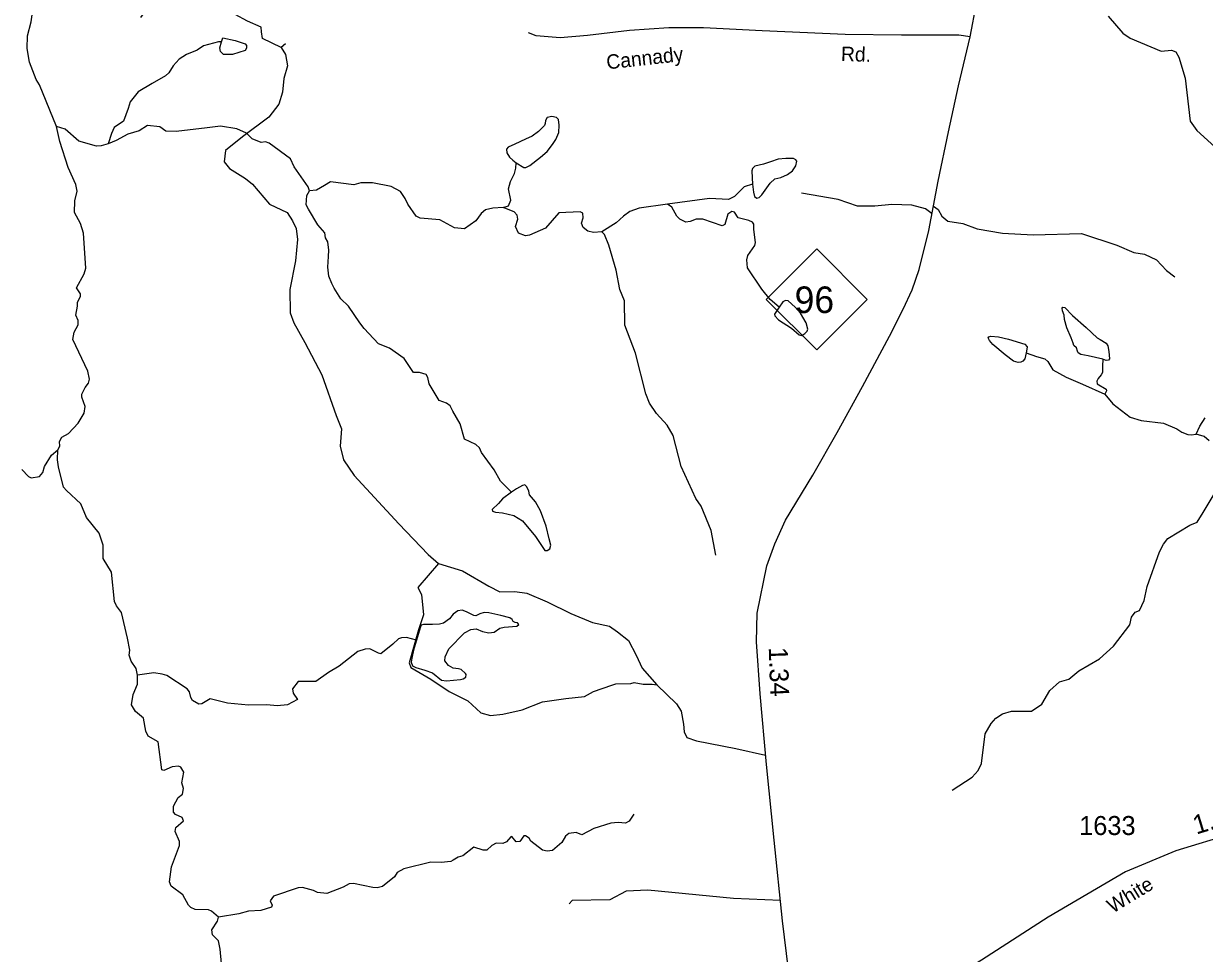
# Model space of a CAD drawing. Extents: x 2056842 to 2160602, y 826753 to 1016856.
# Drawn here: x 2118145 to 2125925, y 874725 to 880850 of the extents above; entities that cross this region are included whole.
import ezdxf

# ---------------------------------------------------------------- set-up
doc = ezdxf.new("R2010")
doc.units = 0
for name, color, linetype in [('Exist Hydrographic Creek Single Shore', 7, 'Continuous'), ('Exist Hydrographic Misc Water Feature', 7, 'Continuous'), ('Exist Road Non-System Type 51', 7, 'Continuous'), ('Exist Road Primary NC Attributed', 7, 'Continuous'), ('Exist Road Primary NC Service Mileage Hundredths English Label', 7, 'Continuous'), ('Exist Road Primary NC Shield CELL', 7, 'Continuous'), ('Exist Road Primary NC Shield Number Label', 7, 'Continuous'), ('Exist Road Secondary Mileage Hundredths English Label', 7, 'Continuous'), ('Exist Road Secondary Type 41 Attributed', 7, 'Continuous'), ('Exist Road Secondary Type 51 Attributed', 7, 'Continuous'), ('Exist Road Secondary Type 51 Label', 7, 'Continuous'), ('Exist Road Secondary Type 51 Number Label', 7, 'Continuous')]:
    doc.layers.add(name, color=color, linetype=linetype)

msp = doc.modelspace()

# ---------------------------------------------------------------- linework, layer by layer
at = {"layer": 'Exist Hydrographic Creek Single Shore'}
for points in [[(2118362.2, 880170.9), (2118249.1, 880446.6), (2118226.8, 880480.5), (2118184.3, 880596.2), (2118168.1, 880686.1), (2118171.8, 880770), (2118195.4, 880862.1), (2118245.6, 881212.4), (2118249.5, 881260.2), (2118281.3, 881336.4), (2118292.9, 881406.7), (2118336.4, 881494.7), (2118378, 881554.8), (2118441.9, 881629), (2118489.4, 881705.4), (2118644.8, 881889.9), (2118769.8, 882062.5), (2118845.2, 882200.7), (2118936.8, 882299.2), (2119076.3, 882413.8)], [(2120028, 879748.6), (2120020, 879774.5), (2119927.3, 879906.1), (2119903.1, 879958), (2119762.8, 880063.3), (2119738.8, 880071.2), (2119710.7, 880067.1), (2119650.5, 880090.8), (2119614.6, 880128.7), (2119550.2, 880156.3), (2119442.3, 880174), (2119354.2, 880163.5), (2119150.5, 880138.6), (2119082.5, 880142.3), (2119042.3, 880170.1), (2118962.3, 880177.8), (2118906.5, 880143.5), (2118832.5, 880121.3), (2118754.8, 880078.9), (2118702.7, 880058.6)], [(2118369.6, 878041.4), (2118383.5, 878065.4), (2118381.2, 878097.3), (2118397.3, 878125.5), (2118441.1, 878149.5), (2118504.8, 878218.1), (2118544.6, 878284.2), (2118550.4, 878328), (2118528.1, 878390.2), (2118527.8, 878409.9), (2118549.7, 878452.1), (2118571.6, 878482.1), (2118579.4, 878508.2), (2118567.3, 878560.3), (2118470.3, 878769.7), (2118478.2, 878817.7), (2118504.1, 878865.7), (2118503.7, 878894), (2118489.7, 878929.7), (2118499.4, 878987.9), (2118501.2, 879011.8), (2118519.2, 879053.8), (2118519.2, 879069.8), (2118492.8, 879109.8), (2118544.5, 879201.9), (2118554.5, 879238.1), (2118539.3, 879470), (2118518.9, 879533.8), (2118480.7, 879605.8), (2118482.3, 879681.5), (2118498, 879745.5), (2118489.8, 879789.6), (2118439.3, 879901.3), (2118382.8, 880073), (2118362.2, 880170.9)], [(2118702.7, 880058.6), (2118657, 880044.5), (2118625, 880042.3), (2118508.7, 880075.7), (2118418.5, 880153.5), (2118362.5, 880171.2)], [(2121304.2, 879638.3), (2121236.3, 879633.9), (2121188.1, 879623.7), (2121160.5, 879599.6), (2121124.8, 879551.4), (2121051, 879499), (2120983.1, 879504.9), (2120886.7, 879556.4), (2120758.8, 879567.8), (2120730.5, 879581.7), (2120676.3, 879659.5), (2120659.9, 879697.3), (2120627.9, 879743.3), (2120567.7, 879777), (2120443.8, 879800.4), (2120367.7, 879800.1), (2120319.7, 879787.9), (2120167.8, 879807.2), (2120127.8, 879783), (2120075.9, 879752.8), (2120028, 879748.6)], [(2121358.8, 877763.4), (2121286.2, 877836.4), (2121245.8, 877910.2), (2121161.5, 878023.8), (2121149.2, 878055.8), (2121125.2, 878077.6), (2121051, 878111.4), (2121020.4, 878213.2), (2120972.2, 878296.9), (2120956, 878332.9), (2120932, 878348.8), (2120882, 878366.5), (2120817.4, 878476.2), (2120809.2, 878518.2), (2120797.3, 878538.2), (2120753.2, 878551.9), (2120713.2, 878551.8), (2120652.7, 878643.6), (2120556.6, 878711), (2120483.1, 878740.6), (2120418.7, 878808.2), (2120388.6, 878841.5), (2120359.5, 878878.9), (2120285.8, 878989), (2120235.9, 879037.9), (2120190.8, 879107.4), (2120174.8, 879137.3), (2120157, 879186.3), (2120148.7, 879245.6), (2120154.9, 879316.2), (2120155.9, 879357.8), (2120148.7, 879412.9), (2120134.1, 879437.8), (2120128.9, 879471.1), (2120084.3, 879524.1), (2120022.4, 879626.6), (2120006.4, 879656.5), (2120010.3, 879716.5), (2120028, 879748.6)], [(2121954.8, 879477.1), (2121899.1, 879472.9), (2121862.8, 879482.6), (2121830.8, 879506.5), (2121820.7, 879534.5), (2121832.4, 879570.5), (2121830.2, 879600.5), (2121812.3, 879610.5), (2121672.3, 879603.8), (2121582.7, 879501.5), (2121478.9, 879457), (2121451, 879451), (2121405.1, 879468.7), (2121386.8, 879512.6), (2121400.6, 879560.7), (2121396.5, 879588.6), (2121376.2, 879610.5), (2121304.2, 879638.3)], [(2122387.9, 879661), (2122200.3, 879634.2), (2122140.2, 879611.9), (2122096.5, 879581.8), (2122048.5, 879537.5), (2121954.8, 879477.1)], [(2123122.6, 878982.6), (2123064.6, 879032), (2123008.2, 879099.8), (2122913.7, 879241.4), (2122909.6, 879293.3), (2122917.5, 879321.4), (2122963.1, 879387.6), (2122967, 879407.6), (2122956.5, 879493.5), (2122956.5, 879529.5), (2122948.5, 879541.5), (2122924.3, 879553.4), (2122852.1, 879571.1), (2122828.1, 879606.9), (2122811.9, 879612.8), (2122784.3, 879594.8), (2122764.6, 879526.7), (2122748.4, 879518.6), (2122620.2, 879562), (2122576.5, 879561.8), (2122536.6, 879545.7), (2122508.5, 879541.6), (2122468.5, 879561.4), (2122448.2, 879581.3), (2122416, 879641.1), (2122387.9, 879661)], [(2118134.3, 877912.4), (2118178.3, 877866.5), (2118194.5, 877858.6), (2118250.5, 877867), (2118272.4, 877892.8), (2118282, 877933), (2118327.9, 878007.1), (2118369.6, 878041.4)], [(2118896, 876558), (2118885.7, 876601.8), (2118853.6, 876649.8), (2118841.6, 876689.7), (2118845.2, 876721.8), (2118828.8, 876801.5), (2118790.4, 876971.3), (2118756.2, 877015.3), (2118744, 877043.1), (2118725, 877237.1), (2118668.8, 877326.8), (2118670.3, 877414.7), (2118642, 877492.7), (2118559.5, 877596.2), (2118523, 877686.2), (2118426.7, 877773.8), (2118408.8, 877795.5), (2118374.2, 877929.4), (2118367.9, 877977.4), (2118369.6, 878041.4)], [(2120734.5, 876788.7), (2120666.7, 876805.9), (2120634.7, 876803.6), (2120614.8, 876797.6), (2120577.1, 876761.5), (2120499.2, 876699.2), (2120483.2, 876703.1), (2120427.2, 876730.8), (2120395.2, 876728.7), (2120347.2, 876714.4), (2120223.8, 876618), (2120154.1, 876575.6), (2120070.2, 876515.3), (2119954.3, 876516.8), (2119916.4, 876468.6), (2119920.5, 876438.6), (2119948.8, 876396.7), (2119883, 876362.5), (2119814.9, 876356.2), (2119747, 876361.8), (2119627.1, 876361.3), (2119489.1, 876372.7), (2119374.7, 876402.2), (2119319.1, 876368), (2119299, 876367.9), (2119258.8, 876391.7), (2119246.7, 876411.7), (2119238.7, 876447.6), (2119222.5, 876467.6), (2119088.2, 876554.9), (2119058.3, 876564.7), (2119002.1, 876572.5), (2118896.3, 876558.1)], [(2119429, 874964.6), (2119382.9, 875004.2), (2119362.7, 875012.2), (2119274.8, 875013.7), (2119246.5, 875027.7), (2119230.8, 875043.8), (2119194.5, 875111.5), (2119118.2, 875167.2), (2119106, 875197), (2119119.5, 875295.1), (2119173, 875435.4), (2119172.9, 875463.3), (2119144.7, 875527.2), (2119148.5, 875555), (2119198.3, 875599.3), (2119190.3, 875621.4), (2119146, 875639.1), (2119131.9, 875655.1), (2119131.7, 875695.1), (2119163.4, 875751.3), (2119191.4, 875773.3), (2119199.1, 875811.5), (2119187.1, 875849.2), (2119200.7, 875919.4), (2119180.7, 875951.4), (2119164.8, 875959.2), (2119124.7, 875955.1), (2119068.7, 875930.7), (2119056.6, 875934.6), (2119031.9, 876118.5), (2118965.8, 876156.3), (2118949.7, 876188.1), (2118935.4, 876274), (2118883.1, 876317.8), (2118854.9, 876361.7), (2118866.8, 876429.7), (2118894.4, 876498), (2118896, 876558)], [(2120975.3, 875339.5), (2120959.3, 875331.4), (2120897.2, 875323.2), (2120827.2, 875326.8), (2120649.5, 875282), (2120605.8, 875257.8), (2120589.8, 875229.8), (2120510, 875165.4), (2120473.9, 875157.3), (2120446.1, 875159.1), (2120317.9, 875186.6), (2120290, 875182.5), (2120250, 875162.3), (2120142.2, 875119.7), (2120082.3, 875125.5), (2120054.2, 875139.4), (2119982.2, 875159.1), (2119954.3, 875157), (2119790.5, 875102.3), (2119770.4, 875072.2), (2119782.7, 875042.2), (2119778.8, 875030.2), (2119707, 875007.9), (2119627.1, 875003.5), (2119562.9, 874985.2), (2119429, 874964.7)], [(2119454.7, 874588.7), (2119440, 874752.7), (2119429.7, 874808.7), (2119389.5, 874848.2), (2119385.2, 874880.5), (2119423.2, 874938.4), (2119429, 874964.6)]]:
    msp.add_lwpolyline(points, dxfattribs=at)
at = {"layer": 'Exist Hydrographic Misc Water Feature'}
for points in [[(2125290, 880899.5), (2125388.4, 880786.1), (2125436.6, 880754.3), (2125641, 880669.2), (2125708.9, 880675.4), (2125737, 880663.5), (2125757.1, 880627.6), (2125797.7, 880489.9), (2125830.9, 880206.1), (2125875.2, 880146.3), (2126017.7, 880015), (2126096.1, 879963.3), (2126160, 879945.5), (2126232.2, 879919.9), (2126252.3, 879903.9), (2126340.7, 879774.4), (2126387, 879722.5), (2126555.4, 879599.4), (2126729.9, 879492.2), (2126872.4, 879386.8), (2126988.7, 879273.4), (2127022.9, 879265.5), (2127064.7, 879261.3), (2127113.5, 879261.3)], [(2119449.7, 880729.9), (2119429.8, 880729.8), (2119330, 880703.3), (2119287.9, 880675.1), (2119218.2, 880646.9), (2119170.2, 880614.6), (2119130.4, 880572.5), (2119102.8, 880526.4), (2119080.8, 880506.3), (2118991, 880455.9), (2118899.3, 880399.5), (2118847.5, 880335.2), (2118833.7, 880291.3), (2118804.2, 880207.1), (2118742.5, 880164.8), (2118724.4, 880126.7), (2118702.7, 880058.6)], [(2119492.2, 880646.1), (2119462.2, 880645.9), (2119441.9, 880665.8), (2119438, 880689.8), (2119449.7, 880729.9)], [(2119449.7, 880729.9), (2119457.7, 880755.9), (2119539.7, 880738.3)], [(2119539.7, 880738.3), (2119605.8, 880716.5), (2119613.7, 880704.5), (2119614, 880688.5), (2119603.9, 880672.6), (2119522.3, 880646.2), (2119492.2, 880646.1)], [(2121391, 879932.6), (2121440.9, 879902.4), (2121454.4, 879902.4), (2121480.3, 879914.9), (2121551, 879968.9), (2121594.6, 880007.4), (2121629.9, 880054.2), (2121650.7, 880085.3), (2121670.4, 880133.1), (2121673.5, 880179.9), (2121668.3, 880217.3), (2121656.9, 880230.8), (2121625.8, 880238.1), (2121595.6, 880230.8), (2121583.2, 880212.1), (2121581.1, 880192.4), (2121575.9, 880178.9), (2121536.4, 880139.4), (2121494.9, 880109.2), (2121452.3, 880088.5), (2121380.6, 880055.2), (2121338, 880035.5), (2121327.6, 880023), (2121328.7, 879998), (2121345.3, 879968.9), (2121369.2, 879949.2), (2121391, 879932.6)], [(2122947, 879791.2), (2122953.3, 879739.2), (2122961.6, 879710.1), (2122975.1, 879700.8), (2122990.7, 879703.9), (2123009.4, 879722.6), (2123064.4, 879798.5), (2123095.6, 879826.5), (2123135, 879836.9), (2123178.7, 879855.6), (2123210.9, 879880.6), (2123233.7, 879913.8), (2123238.9, 879942.9), (2123232.7, 879953.3), (2123217.1, 879960.6), (2123166.2, 879961.7), (2123117.4, 879956.5), (2123065.5, 879938.8), (2123020.8, 879924.2), (2122963.7, 879910.7), (2122947, 879896.2), (2122942.9, 879880.6), (2122946, 879834.9), (2122947, 879791.2)], [(2121304.2, 879638.3), (2121340.3, 879650.4), (2121356.1, 879686.5), (2121339.7, 879762.3), (2121353.4, 879810.4), (2121379.2, 879862.5), (2121387.9, 879897.2), (2121391, 879932.6)], [(2122947, 879791.2), (2122891.5, 879775.1), (2122829.8, 879711), (2122789.8, 879690.8), (2122663.7, 879698.1), (2122387.9, 879661)], [(2122705.9, 877348.8), (2122675.2, 877510.7), (2122608.7, 877670.3), (2122574.5, 877722.1), (2122477.5, 877931.6), (2122424.8, 878137.4), (2122384.2, 878205.3), (2122314.1, 878280.8), (2122269.8, 878350.6), (2122245.4, 878410.5), (2122176.3, 878678.2), (2122105.5, 878863.9), (2122104.7, 879023.8), (2122072.5, 879097.7), (2122050, 879225.5), (2122001.2, 879389.3), (2121973.1, 879461.2), (2121954.8, 879477.1)], [(2123122.6, 878982.6), (2123092.5, 878935.8), (2123094.5, 878924.4), (2123118.4, 878898.4), (2123203.6, 878844.4), (2123254.5, 878799.7), (2123273.2, 878795.5), (2123292.9, 878809), (2123308.5, 878823.6), (2123311.6, 878836), (2123301.2, 878878.7), (2123262.8, 878943.1), (2123228.5, 878981.6), (2123181.8, 879024.2), (2123164.1, 879026.2), (2123146.5, 879016.9), (2123122.6, 878982.6)], [(2125255.2, 878638.6), (2125158.6, 878660.4), (2125110.8, 878670.8), (2125093.1, 878680.1), (2125087.9, 878691.6), (2125082.7, 878713.4), (2125065.1, 878730), (2125059.9, 878744.6), (2125047.4, 878778.9), (2125018.3, 878846.4), (2125002.7, 878901.5), (2125000.7, 878928.5), (2124990.3, 878957.6), (2124988.2, 878976.3), (2124991.3, 878981.5), (2125004.8, 878979.5), (2125056.8, 878927.5), (2125146.1, 878848.5), (2125217.8, 878780.9), (2125238.5, 878768.5), (2125277, 878745.6), (2125288.4, 878726.9), (2125295.7, 878690.5), (2125299.8, 878640.6), (2125293.6, 878632.3), (2125277, 878631.3), (2125255.2, 878638.6)], [(2124750.3, 878682.2), (2124742, 878642.7), (2124728.5, 878626.1), (2124715, 878618.8), (2124698.4, 878616.7), (2124666.2, 878626.1), (2124612.2, 878667.7), (2124531.1, 878735.2), (2124508.3, 878763.3), (2124501, 878779.9), (2124505.2, 878786.1), (2124516.6, 878790.3), (2124568.5, 878787.2), (2124635, 878771.6), (2124741, 878737.3), (2124757.6, 878721.7), (2124755.5, 878706.1), (2124750.3, 878682.2)], [(2124750.3, 878682.2), (2124818, 878655.9), (2124873.9, 878642.1), (2124894, 878624.2), (2124926.2, 878568.3), (2125014.4, 878520.7), (2125120.6, 878475.2), (2125268.9, 878408)], [(2125255.2, 878638.6), (2125254.1, 878593.9), (2125253.1, 878552.3), (2125243.7, 878535.7), (2125224, 878512.8), (2125216.7, 878494.1), (2125218.6, 878477.7), (2125276.7, 878441.9), (2125278.7, 878431.9), (2125268.9, 878408)], [(2125268.9, 878408), (2125321.2, 878346.1), (2125435.4, 878256.6), (2125507.8, 878235), (2125655.6, 878217.6), (2125744, 878180), (2125776, 878158.2), (2125816, 878142.3), (2125837.9, 878140.7), (2125871.1, 878144.9)], [(2125871.1, 878144.9), (2125894, 878198.9), (2125930.3, 878252.5)], [(2125956.2, 878101), (2125924, 878130.8), (2125871.1, 878144.9)], [(2121358.8, 877763.4), (2121300.6, 877719.8), (2121274.7, 877689.6), (2121233.1, 877650.2), (2121234.1, 877638.7), (2121253.9, 877631.4), (2121300.6, 877627.3), (2121375.4, 877609.6), (2121432.5, 877574.3), (2121517.7, 877472.4), (2121565.5, 877399.7), (2121580.1, 877379.9), (2121594.6, 877378.9), (2121611.2, 877389.3), (2121619.5, 877413.2), (2121608.1, 877455.8), (2121588.4, 877538.9), (2121551, 877640.8), (2121516.7, 877700), (2121478.3, 877745.8), (2121473.1, 877770.7), (2121461.6, 877797.7), (2121448.1, 877811.3), (2121432.5, 877808.1), (2121393.1, 877785.3), (2121358.8, 877763.4)], [(2124262.5, 875799.9), (2124394.1, 875886.4), (2124433.9, 875930.6), (2124455.6, 875976.7), (2124481.1, 876170.8), (2124518.8, 876238.9), (2124550.4, 876275.1), (2124594.3, 876303.3), (2124654.1, 876321.6), (2124786.2, 876320.1), (2124854.1, 876366.4), (2124907.4, 876456.7), (2124971.1, 876514.9), (2125031.2, 876531.1), (2125097, 876585.5), (2125232.8, 876666), (2125326.3, 876748.4), (2125433.5, 876888.9), (2125445.4, 876940.9), (2125469.2, 876973), (2125497.3, 876983.2), (2125528.9, 877049.3), (2125548.4, 877141.4), (2125629.4, 877369.7), (2125655.2, 877421.8), (2125682.9, 877457.8), (2125828.7, 877546.4), (2125876.4, 877566.7), (2125916.2, 877628.9), (2126001.7, 877773.2)], [(2120734.5, 876788.7), (2120713.7, 876723.3), (2120702.3, 876670.3), (2120699.2, 876644.3), (2120706.5, 876620.4), (2120729.3, 876607.9), (2120789.6, 876591.3), (2120838.4, 876572.6), (2120897.6, 876525.8), (2120931.9, 876520.6), (2121024.3, 876528.9), (2121042, 876534.1), (2121058.6, 876545.5), (2121061.7, 876563.2), (2121056.5, 876569.4), (2121028.5, 876594.4), (2121009.8, 876599.6), (2120975.5, 876603.7), (2120945.4, 876621.4), (2120920.5, 876651.6), (2120921.5, 876679.6), (2120947.5, 876731.6), (2121049.3, 876836.6), (2121091.8, 876858.4), (2121126.1, 876862.5), (2121168.7, 876845.9), (2121210.3, 876836.6), (2121244.5, 876841.8), (2121283, 876866.7), (2121312.1, 876874), (2121394.1, 876880.2), (2121408.7, 876890.6), (2121399.3, 876902), (2121384.8, 876904.1), (2121370.2, 876912.4), (2121365, 876924.9), (2121348.4, 876935.3), (2121288.2, 876951.9), (2121209.2, 876968.6), (2121180.1, 876970.6), (2121150, 876961.3), (2121125.1, 876947.8), (2121110.5, 876951.9), (2121063.8, 876974.8), (2121034.7, 876986.2), (2121006.7, 876982.1), (2120975.5, 876959.2), (2120951.6, 876928), (2120912.1, 876900), (2120885.1, 876894.8), (2120839.4, 876890.6), (2120780.2, 876892.7), (2120764.6, 876887.5), (2120759.4, 876877.1), (2120734.5, 876788.7)], [(2122165.8, 875642.6), (2122134, 875596.5), (2122110.1, 875582.4), (2122062.1, 875588.2), (2122013.9, 875582), (2121902.3, 875547.5), (2121822.2, 875507.2), (2121786.3, 875521), (2121738.3, 875514.8), (2121714.5, 875496.7), (2121690.5, 875456.5), (2121628.8, 875402.3), (2121594.8, 875398.2), (2121562.8, 875406.1), (2121486.5, 875463.7), (2121476.4, 875483.6), (2121452.5, 875499.6), (2121440.6, 875499.5), (2121414.5, 875461.4), (2121390.5, 875459.2), (2121362.4, 875495.1), (2121354.4, 875493.1), (2121326.5, 875461), (2121302.8, 875448.9), (2121258.7, 875450.7), (2121230.8, 875436.5), (2121197, 875404.5), (2121173, 875404.3), (2121110.8, 875424), (2121039.1, 875367.8), (2121007.1, 875359.7), (2120975.3, 875339.5)]]:
    msp.add_lwpolyline(points, dxfattribs=at)
at = {"layer": 'Exist Road Non-System Type 51'}
for points in [[(2119871.5, 880716.4), (2119842.4, 880691.8), (2119718.8, 880752.6), (2119713.1, 880796.4), (2119709.3, 880826.8), (2119620, 880866.7), (2119538.3, 880910.5), (2119405.3, 880961.8), (2119167.8, 880999.8), (2119067.1, 881003.7), (2119010, 880986.5), (2118951.1, 880939), (2118915, 880889.6)], [(2119842.4, 880691.8), (2119869.9, 880647.1), (2119883.2, 880571.1), (2119860.4, 880487.4), (2119850.9, 880398), (2119826.2, 880318.1), (2119761.6, 880232.6), (2119586.8, 880103.3), (2119475.6, 880014.9), (2119466.1, 879938.8), (2119502.2, 879895.1), (2119606.7, 879830.4), (2119652.3, 879792.4), (2119764.4, 879661.2), (2119882.3, 879606), (2119917.4, 879549.9), (2119940.2, 879500.5), (2119949.7, 879428.2), (2119936.4, 879287.5), (2119898.4, 879099.3), (2119901.3, 878944.3), (2119926, 878877.7), (2119998.2, 878748.4), (2120110.3, 878535.5), (2120204.4, 878268.3), (2120238.6, 878180.8), (2120231, 878066.7), (2120251.9, 877977.4), (2120322.2, 877872.8), (2120617.7, 877554.3), (2120811.5, 877352.7), (2120878, 877293.8)], [(2124130.1, 879596.2), (2124087, 879630.3), (2123997.7, 879653.1), (2123864.7, 879658.8), (2123754.5, 879647.4), (2123638.6, 879647.4), (2123512.2, 879692.1), (2123270.9, 879733.9)], [(2124139.6, 879646.2), (2124169.7, 879625.5), (2124194.4, 879581.8), (2124234.3, 879549.5), (2124333.1, 879532.3), (2124428.1, 879498.1), (2124593.5, 879469.6), (2124796.8, 879458.2), (2125116, 879467.7), (2125346.9, 879390.7), (2125459, 879343.1), (2125529.3, 879331.7), (2125609.1, 879293.7), (2125675.7, 879223.3), (2125730.8, 879181.5)], [(2120878, 877293.8), (2120742.1, 877135), (2120766.8, 877089.3), (2120780.1, 876954.3), (2120747.8, 876855.5), (2120686.1, 876639.6), (2120695.6, 876609.2), (2120828.6, 876531.2), (2120948.3, 876449.5), (2121071.8, 876388.6), (2121156.9, 876309.2), (2121220.5, 876292.1), (2121302.2, 876300.7), (2121429.5, 876330.2), (2121563.5, 876381.5), (2121717, 876403.8), (2121840.5, 876417.2), (2121899.4, 876449.5), (2122020, 876492.3), (2122047.6, 876501.8), (2122145.9, 876504.1), (2122166.8, 876509.9), (2122227.6, 876498.4), (2122285.6, 876498.4), (2122316.5, 876495.1)], [(2120878, 877293.8), (2121036.7, 877245.3), (2121209.6, 877144.5), (2121281.8, 877106.5), (2121382.5, 877108.4), (2121460.4, 877098.9), (2121595.3, 877039.9), (2121751.2, 876963.8), (2121892.7, 876903.9), (2122004.8, 876881.1), (2122058, 876843.1), (2122130.3, 876786.1), (2122181.6, 876689.1), (2122219.6, 876603.5), (2122316.5, 876495.1)], [(2122316.5, 876495.1), (2122447.1, 876370.1), (2122477.5, 876319.7), (2122492.3, 876235.6), (2122497, 876185.2), (2122514.1, 876147.1), (2122577.8, 876125.3), (2122838.1, 876075.8), (2123033.8, 876031)], [(2123132, 875073.4), (2122821.5, 875087.5), (2122257.1, 875142.7), (2122115.5, 875136), (2122007.2, 875078.9), (2121760.2, 875073.2), (2121739.3, 875052.3)]]:
    msp.add_lwpolyline(points, dxfattribs=at)
at = {"layer": 'Exist Road Primary NC Attributed'}
for points in [[(2124380.8, 880762.7), (2124424, 880982.8), (2124463.9, 881161.5), (2124531.4, 881487.6)], [(2123312.1, 873979.7), (2123261.7, 874118.5), (2123213.7, 874383.3), (2123145.8, 874939), (2123091.2, 875471.9), (2123039.4, 875969.6), (2122997.1, 876434), (2122972.9, 876776.7), (2122977.6, 876965.9), (2123041.8, 877277.3), (2123095, 877423.7), (2123164.8, 877578.2), (2123343.9, 877874.4), (2123504.4, 878156.7), (2123672.1, 878459.5), (2123850.8, 878790.4), (2123939.6, 878968.7), (2124000.4, 879096.1), (2124046, 879231.1), (2124109.7, 879487.8), (2124170.9, 879812.4), (2124238.4, 880137.6), (2124305.4, 880440.4), (2124380.8, 880762.7)]]:
    msp.add_lwpolyline(points, dxfattribs=at)
at = {"layer": 'Exist Road Primary NC Shield CELL'}
msp.add_lwpolyline([(2123037.6, 879033.1), (2123370.6, 879366.1), (2123703.6, 879033.1), (2123370.6, 878700.1)], close=True, dxfattribs=at)
at = {"layer": 'Exist Road Secondary Type 41 Attributed'}
msp.add_lwpolyline([(2124380.8, 880762.7), (2124307.5, 880774.4), (2123929.3, 880774.4), (2123556.9, 880778.2), (2123010.6, 880802), (2122624.8, 880821), (2122396.8, 880822.9), (2122136.5, 880803.9), (2121860, 880770.6), (2121679.5, 880755.4), (2121521.8, 880768.7), (2121470.5, 880788.3)], dxfattribs=at)
at = {"layer": 'Exist Road Secondary Type 51 Attributed'}
msp.add_lwpolyline([(2129102.1, 875080.9), (2129037.5, 875082.8), (2128868.4, 875109.4), (2128574.8, 875194), (2128067.5, 875344.2), (2127390.1, 875541), (2127063.2, 875588.6), (2126721.2, 875590.5), (2126364, 875562), (2126112.2, 875515.4), (2125736, 875401.3), (2125405.3, 875262.5), (2124895.1, 874964.9), (2124457.1, 874680.6), (2123727.5, 874235.7), (2123312.1, 873979.7)], dxfattribs=at)

# ---------------------------------------------------------------- texts
at = {"layer": 'Exist Road Primary NC Service Mileage Hundredths English Label'}
msp.add_text('1.34', height=125, rotation=271.88108, dxfattribs=at).set_placement((2123054.3, 876740.6))
at = {"layer": 'Exist Road Primary NC Shield Number Label'}
msp.add_text('96', height=175, dxfattribs=at).set_placement((2123224.8, 878943.4))
at = {"layer": 'Exist Road Secondary Mileage Hundredths English Label'}
msp.add_text('1.19', height=125, rotation=16.86922, dxfattribs=at).set_placement((2125871.2, 875507.6))
at = {"layer": 'Exist Road Secondary Type 51 Label'}
for s, rotation, p in [('Cannady', 6.32903, (2121989.9, 880547.9)), ('Rd.', 358.01909, (2123529, 880604.2)), ('White', 31.30809, (2125320.6, 874986.7))]:
    msp.add_text(s, height=95, rotation=rotation, dxfattribs=at).set_placement(p)
at = {"layer": 'Exist Road Secondary Type 51 Number Label'}
msp.add_text('1633', height=125, dxfattribs=at).set_placement((2125099.5, 875505))

doc.saveas('drawing.dxf')
